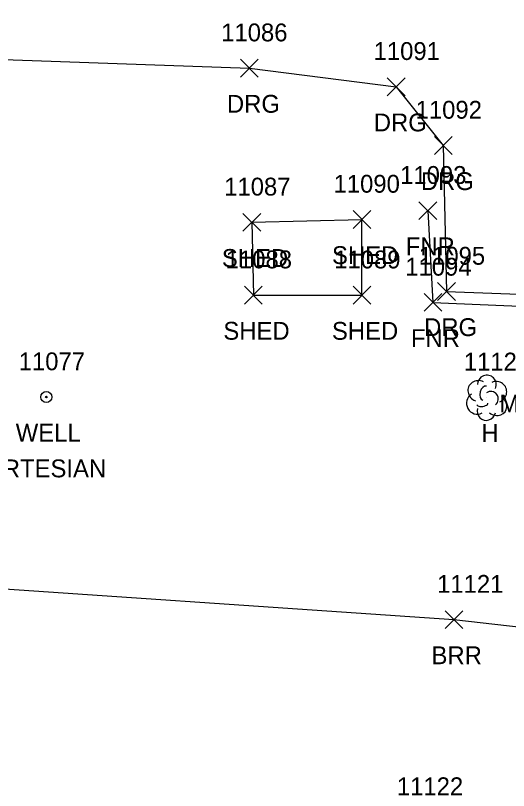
# Model space of a CAD drawing. Extents: x 1482574 to 1485769, y 580696 to 595649.
# Drawn here: x 1483701.6 to 1483756.9, y 582869.5 to 582956.3 of the extents above; entities that cross this region are included whole.
import ezdxf

# ---------------------------------------------------------------- set-up
doc = ezdxf.new("R2010")
doc.units = 0
for name, color, linetype in [('L_A', 7, 'Continuous'), ('L_I', 7, 'Continuous'), ('L_TIC', 7, 'Continuous'), ('LABL', 7, 'Continuous'), ('LBC', 7, 'Continuous'), ('LFNC', 7, 'Continuous'), ('LTD', 7, 'Continuous'), ('R_A', 7, 'Continuous'), ('R_I', 7, 'Continuous'), ('R_TIC', 7, 'Continuous'), ('RDG', 7, 'Continuous'), ('U_A', 7, 'Continuous'), ('U_C', 7, 'Continuous'), ('U_I', 7, 'Continuous'), ('UWW', 7, 'Continuous')]:
    doc.layers.add(name, color=color, linetype=linetype)

msp = doc.modelspace()

# ---------------------------------------------------------------- linework, layer by layer
at = {"layer": 'L_TIC'}
for points in [[(1483746.824, 582933.454), (1483748.824, 582935.454)], [(1483748.824, 582933.454), (1483746.824, 582935.454)], [(1483727.097, 582932.151), (1483729.097, 582934.151)], [(1483729.097, 582932.151), (1483727.097, 582934.151)], [(1483727.097, 582932.151), (1483729.097, 582934.151)], [(1483729.097, 582932.151), (1483727.097, 582934.151)], [(1483739.446, 582932.47), (1483741.446, 582934.47)], [(1483741.446, 582932.47), (1483739.446, 582934.47)], [(1483739.446, 582932.47), (1483741.446, 582934.47)], [(1483741.446, 582932.47), (1483739.446, 582934.47)], [(1483727.265, 582923.99), (1483729.265, 582925.99)], [(1483729.265, 582923.99), (1483727.265, 582925.99)], [(1483739.44, 582923.983), (1483741.44, 582925.983)], [(1483741.44, 582923.983), (1483739.44, 582925.983)], [(1483747.4, 582923.172), (1483749.4, 582925.172)], [(1483749.4, 582923.172), (1483747.4, 582925.172)], [(1483749.757, 582887.619), (1483751.757, 582889.619)], [(1483751.757, 582887.619), (1483749.757, 582889.619)]]:
    msp.add_lwpolyline(points, dxfattribs=at)
at = {"layer": 'LABL'}
msp.add_lwpolyline([(1483294.582, 582902.077), (1483334.431, 582902.169), (1483361.39, 582901.358), (1483408.739, 582891.819), (1483422.625, 582892.924), (1483440.454, 582909.758), (1483472.105, 582896.667), (1483512.822, 582891.045), (1483577.567, 582895.541), (1483642.957, 582897.054), (1483689.36, 582892.829), (1483750.757, 582888.619), (1483798.359, 582883.228), (1483823.862, 582883.532), (1483871.202, 582884.654), (1483912.082, 582881.621), (1483947.923, 582878.175)], dxfattribs=at)
at = {"layer": 'LBC'}
for points in [[(1483728.097, 582933.151), (1483728.265, 582924.99), (1483740.44, 582924.983), (1483740.446, 582933.47)], [(1483728.097, 582933.151), (1483740.446, 582933.47)]]:
    msp.add_lwpolyline(points, dxfattribs=at)
at = {"layer": 'LFNC'}
msp.add_lwpolyline([(1483747.824, 582934.454), (1483748.4, 582924.172), (1483769.614, 582923.256)], dxfattribs=at)
at = {"layer": 'LTD'}
msp.add_line((1483754.407, 582913.538), (1483754.407, 582913.538), dxfattribs=at)
msp.add_line((1483754.407, 582913.538), (1483754.407, 582913.538), dxfattribs=at)
msp.add_arc((1483754.454, 582914.972), 1.047, 335.52715, 180.95627, dxfattribs=at)
for centre, major_axis, ratio, start_param, end_param in [((1483753.615, 582914.205), (1.21, -0.512), 0.895232, 1.570796, 4.712389), ((1483754.198, 582913.997), (-0.208, -0.792), 0.645439, 3.141593, 6.283185), ((1483755.448, 582914.122), (-1.141, -0.483), 0.949671, 1.570796, 4.712389), ((1483753.324, 582912.83), (0.584, -1.042), 0.959034, 3.141593, 6.283185), ((1483754.907, 582913.372), (-0.5, 0.667), 0.989748, 3.141593, 6.283185), ((1483755.407, 582912.705), (-1.09, 0.792), 0.841452, 1.570796, 4.712389), ((1483754.407, 582912.038), (0.265, 1.061), 0.942809, 1.570796, 4.712389), ((1483753.949, 582912.788), (-0.625, -0.083), 0.423636, 0, 3.141593)]:
    msp.add_ellipse(centre, major_axis=major_axis, ratio=ratio, start_param=start_param, end_param=end_param, dxfattribs=at)
at = {"layer": 'R_TIC'}
for points in [[(1483726.815, 582949.433), (1483728.815, 582951.433)], [(1483728.815, 582949.433), (1483726.815, 582951.433)], [(1483743.284, 582947.345), (1483745.284, 582949.345)], [(1483745.284, 582947.345), (1483743.284, 582949.345)], [(1483748.562, 582940.763), (1483750.562, 582942.763)], [(1483750.562, 582940.763), (1483748.562, 582942.763)], [(1483748.922, 582924.398), (1483750.922, 582926.398)], [(1483750.922, 582924.398), (1483748.922, 582926.398)]]:
    msp.add_lwpolyline(points, dxfattribs=at)
at = {"layer": 'RDG'}
msp.add_lwpolyline([(1483405.01, 583082.593), (1483413.492, 583085.132), (1483418.474, 583086.112), (1483436.24, 583079.096), (1483449.338, 583066.94), (1483465.272, 583042.951), (1483477.089, 583017.474), (1483496.094, 582986.216), (1483515.207, 582970.799), (1483537.853, 582961.426), (1483582.584, 582953.02), (1483646.085, 582952.506), (1483694.956, 582951.578), (1483727.815, 582950.433), (1483744.284, 582948.345), (1483749.562, 582941.763), (1483749.922, 582925.398), (1483773.279, 582924.547)], dxfattribs=at)
at = {"layer": 'UWW'}
for radius in [0.625, 0.0833]:
    msp.add_circle((1483705.054, 582913.566), radius, dxfattribs=at)

# ---------------------------------------------------------------- texts
at = {"layer": 'L_A'}
for s, p in [('FNR', (1483745.359, 582929.454)), ('SHED', (1483737.084, 582928.47)), ('SHED', (1483737.084, 582928.47)), ('SHED', (1483724.735, 582928.151)), ('SHED', (1483724.735, 582928.151)), ('SHED', (1483724.903, 582919.99)), ('SHED', (1483737.078, 582919.983)), ('FNR', (1483745.936, 582919.172)), ('MMF', (1483755.864, 582911.849)), ('H', (1483753.84, 582908.538)), ('BRR', (1483748.245, 582883.619))]:
    msp.add_text(s, height=2, dxfattribs=at).set_placement(p)
at = {"layer": 'L_I'}
for s, p in [('11093', (1483744.721, 582937.454)), ('11087', (1483724.995, 582936.151)), ('11087', (1483724.995, 582936.151)), ('11090', (1483737.257, 582936.47)), ('11090', (1483737.257, 582936.47)), ('11088', (1483725.162, 582927.99)), ('11089', (1483737.33, 582927.983)), ('11094', (1483745.298, 582927.172)), ('11120', (1483751.863, 582916.538)), ('11121', (1483748.867, 582891.619)), ('11122', (1483744.356, 582868.935))]:
    msp.add_text(s, height=2, dxfattribs=at).set_placement(p)
at = {"layer": 'R_A'}
for p in [(1483725.303, 582945.433), (1483741.772, 582943.345), (1483747.05, 582936.763), (1483747.41, 582920.398)]:
    msp.add_text('DRG', height=2, dxfattribs=at).set_placement(p)
at = {"layer": 'R_I'}
for s, p in [('11086', (1483724.657, 582953.433)), ('11091', (1483741.748, 582951.345)), ('11092', (1483746.46, 582944.763)), ('11095', (1483746.82, 582928.398))]:
    msp.add_text(s, height=2, dxfattribs=at).set_placement(p)
at = {"layer": 'U_A'}
msp.add_text('WELL', height=2, dxfattribs=at).set_placement((1483701.621, 582908.566))
at = {"layer": 'U_C'}
msp.add_text('ARTESIAN', height=2, dxfattribs=at).set_placement((1483698.385, 582904.566))
at = {"layer": 'U_I'}
msp.add_text('11077', height=2, dxfattribs=at).set_placement((1483701.952, 582916.566))

doc.saveas('drawing.dxf')
